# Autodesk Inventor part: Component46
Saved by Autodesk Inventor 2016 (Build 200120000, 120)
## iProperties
Created: 2016-09
Part Number: Component46
Material: Generic
Document SubType Name: Modeling
Designer: Administrator
Appearance: Generic
Author: Administrator
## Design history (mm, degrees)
feature "Body1"
feature "Body2"
feature "Body3"
feature "Body4"
body "Solid1"
body "Solid2"
body "Solid3"
body "Solid4"
